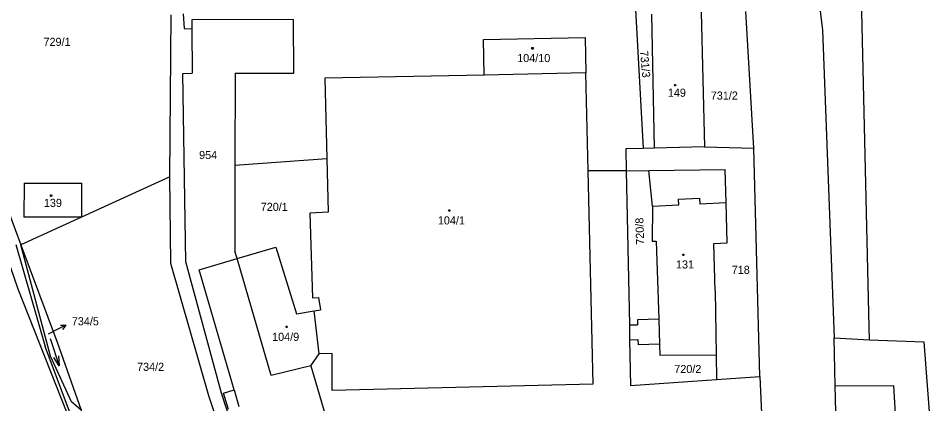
# Model space of a CAD drawing. Extents: x -580551 to -575069, y -1073031 to -1067931.
# Drawn here: x -578576.7 to -578385, y -1071122.8 to -1071041.9 of the extents above; entities that cross this region are included whole.
import ezdxf

# ---------------------------------------------------------------- set-up
doc = ezdxf.new("R2010")
doc.units = 0
for name, color, linetype in [('Druh pozemku', 7, 'Continuous'), ('Hranice z rastru', 7, 'Continuous'), ('Katastrální hranice', 7, 'Continuous'), ('Parcela', 7, 'Continuous'), ('Parcelní číslo', 7, 'Continuous'), ('Parcelní číslo_stavba', 7, 'Continuous'), ('Pomocná vrstva', 7, 'Continuous'), ('SR - hranice státu', 7, 'Continuous'), ('Vnitřní kresba', 7, 'Continuous')]:
    doc.layers.add(name, color=color, linetype=linetype)

msp = doc.modelspace()

# ---------------------------------------------------------------- linework, layer by layer
at = {"layer": 'Druh pozemku'}
msp.add_line((-578569.947, -1071109.134), (-578568.113, -1071114.846), dxfattribs=at)
for points in [[(-578468.59, -1071048.03), (-578468.5, -1071048.18), (-578468.59, -1071048.33), (-578468.77, -1071048.33), (-578468.86, -1071048.18), (-578468.77, -1071048.03)], [(-578438.64, -1071055.75), (-578438.55, -1071055.9), (-578438.64, -1071056.05), (-578438.82, -1071056.05), (-578438.91, -1071055.9), (-578438.82, -1071055.75)], [(-578569.69, -1071078.98), (-578569.6, -1071079.13), (-578569.69, -1071079.28), (-578569.87, -1071079.28), (-578569.96, -1071079.13), (-578569.87, -1071078.98)], [(-578486.06, -1071082.09), (-578485.97, -1071082.24), (-578486.06, -1071082.39), (-578486.24, -1071082.39), (-578486.33, -1071082.24), (-578486.24, -1071082.09)], [(-578436.92, -1071091.43), (-578436.83, -1071091.58), (-578436.92, -1071091.73), (-578437.1, -1071091.73), (-578437.19, -1071091.58), (-578437.1, -1071091.43)], [(-578520.25, -1071106.52), (-578520.16, -1071106.67), (-578520.25, -1071106.82), (-578520.43, -1071106.82), (-578520.52, -1071106.67), (-578520.43, -1071106.52)]]:
    msp.add_lwpolyline(points, close=True, dxfattribs=at)
msp.add_lwpolyline([(-578568.248, -1071112.789), (-578568.113, -1071114.846), (-578569.2, -1071113.095)], dxfattribs=at)
at = {"layer": 'Hranice z rastru'}
msp.add_lwpolyline([(-578566.72, -1070947.779), (-578583.48, -1070998.532), (-578590.876, -1071020.93), (-578592.521, -1071043.374), (-578590.032, -1071060.419), (-578576.797, -1071098.705), (-578560.811, -1071139.089), (-578544.825, -1071179.473), (-578532.639, -1071204.254), (-578528.184, -1071216.579), (-578534.736, -1071226.806), (-578537.749, -1071239.524), (-578532.246, -1071274.139), (-578521.632, -1071309.672), (-578516.391, -1071321.603), (-578520.977, -1071339.96), (-578529.232, -1071361.069)], dxfattribs=at)
at = {"layer": 'Katastrální hranice'}
for p in [(-578577.22, -1071089.4), (-578548.7, -1071170.29)]:
    msp.add_line(p, (-578571.03, -1071110.79), dxfattribs=at)
at = {"layer": 'Parcela'}
for p, q in [((-578397.99, -1071106.73), (-578400.72, -1070989.27)), ((-578412.58, -1071004.4), (-578407.76, -1071044.39)), ((-578447.49, -1071032.19), (-578445.44, -1071069.19)), ((-578433.24, -1071040.55), (-578432.57, -1071068.86)), ((-578422.17, -1071069.12), (-578423.85, -1071040.47)), ((-578544.84, -1071075.2), (-578544.59, -1071041.12)), ((-578542.03, -1071040.93), (-578541.87, -1071044.02)), ((-578518.86, -1071042.13), (-578540.23, -1071042.18)), ((-578540.23, -1071042.18), (-578540.22, -1071044.1)), ((-578518.81, -1071053.37), (-578518.86, -1071042.13)), ((-578443.08, -1071069.13), (-578443.65, -1071041)), ((-578541.87, -1071044.02), (-578540.22, -1071044.1)), ((-578540.22, -1071044.1), (-578540.18, -1071053.43)), ((-578407.76, -1071044.39), (-578405.35, -1071109.02)), ((-578478.99, -1071046.35), (-578457.64, -1071045.89)), ((-578478.81, -1071053.82), (-578478.99, -1071046.35)), ((-578457.64, -1071045.89), (-578457.47, -1071053.34)), ((-578542.14, -1071053.44), (-578540.18, -1071053.43)), ((-578541.52, -1071093.04), (-578542.14, -1071053.44)), ((-578531.15, -1071053.41), (-578531.17, -1071072.74)), ((-578531.15, -1071053.41), (-578518.81, -1071053.37)), ((-578478.81, -1071053.82), (-578512.32, -1071054.45)), ((-578457.47, -1071053.34), (-578478.81, -1071053.82)), ((-578456.99, -1071073.93), (-578457.47, -1071053.34)), ((-578512.32, -1071054.45), (-578511.88, -1071071.31)), ((-578445.44, -1071069.19), (-578449.1, -1071069.28)), ((-578449.1, -1071069.28), (-578449, -1071073.92)), ((-578443.08, -1071069.13), (-578445.44, -1071069.19)), ((-578432.57, -1071068.86), (-578443.08, -1071069.13)), ((-578432.57, -1071068.86), (-578422.17, -1071069.12)), ((-578420.92, -1071117.09), (-578422.17, -1071069.12)), ((-578531.17, -1071072.74), (-578511.88, -1071071.31)), ((-578511.88, -1071071.31), (-578511.58, -1071082.62)), ((-578531.17, -1071072.74), (-578531.18, -1071090.78)), ((-578449, -1071073.92), (-578456.99, -1071073.93)), ((-578455.93, -1071118.76), (-578456.99, -1071073.93)), ((-578449, -1071073.92), (-578444.22, -1071073.85)), ((-578449, -1071073.92), (-578448.34, -1071106.3)), ((-578444.22, -1071073.85), (-578428.22, -1071073.62)), ((-578443.49, -1071081.32), (-578444.22, -1071073.85)), ((-578428.01, -1071080.57), (-578428.22, -1071073.62)), ((-578580.97, -1071076.59), (-578576.15, -1071089.49)), ((-578575.45, -1071076.47), (-578575.48, -1071083.62)), ((-578575.45, -1071076.47), (-578563.39, -1071076.52)), ((-578544.84, -1071075.2), (-578563.43, -1071083.68)), ((-578563.39, -1071076.52), (-578563.43, -1071083.68)), ((-578544.61, -1071093.4), (-578544.84, -1071075.2)), ((-578427.78, -1071089.05), (-578428.01, -1071080.57)), ((-578511.58, -1071082.62), (-578515.44, -1071082.83)), ((-578443.49, -1071081.32), (-578443.56, -1071088.67)), ((-578563.43, -1071083.68), (-578576.15, -1071089.49)), ((-578563.43, -1071083.68), (-578575.48, -1071083.62)), ((-578515.44, -1071082.83), (-578514.89, -1071100.58)), ((-578576.15, -1071089.49), (-578568.52, -1071109.92)), ((-578569.88, -1071112.88), (-578576.15, -1071089.49)), ((-578530.74, -1071092.35), (-578522.6, -1071089.94)), ((-578522.6, -1071089.94), (-578518.22, -1071103.96)), ((-578443.56, -1071088.67), (-578442.68, -1071088.67)), ((-578442.68, -1071088.67), (-578442.15, -1071105.06)), ((-578430.61, -1071089.18), (-578427.78, -1071089.05)), ((-578430.32, -1071099.09), (-578430.61, -1071089.18)), ((-578538.67, -1071094.7), (-578530.74, -1071092.35)), ((-578530.74, -1071092.35), (-578531.18, -1071090.78)), ((-578523.58, -1071116.91), (-578530.74, -1071092.35)), ((-578536.67, -1071121.21), (-578544.61, -1071093.4)), ((-578534.03, -1071120.61), (-578541.52, -1071093.04)), ((-578531.32, -1071119.94), (-578538.67, -1071094.7)), ((-578430.32, -1071099.09), (-578430.1, -1071112.59)), ((-578514.89, -1071100.58), (-578513.63, -1071100.54)), ((-578513.63, -1071100.54), (-578513.21, -1071103.13)), ((-578518.22, -1071103.96), (-578514.56, -1071103.35)), ((-578514.56, -1071103.35), (-578513.21, -1071103.13)), ((-578513.5, -1071112.37), (-578514.56, -1071103.35)), ((-578442.15, -1071105.06), (-578446.64, -1071105.18)), ((-578446.64, -1071105.18), (-578446.61, -1071106.26)), ((-578448.34, -1071106.3), (-578446.61, -1071106.26)), ((-578448.34, -1071106.3), (-578448.28, -1071109.4)), ((-578397.93, -1071109.39), (-578397.99, -1071106.73)), ((-578448.28, -1071109.4), (-578446.54, -1071109.36)), ((-578448.28, -1071109.4), (-578448.08, -1071119.03)), ((-578446.54, -1071109.36), (-578446.51, -1071110.45)), ((-578405.35, -1071109.02), (-578397.93, -1071109.39)), ((-578405.11, -1071119.06), (-578405.35, -1071109.02)), ((-578397.93, -1071109.39), (-578386.49, -1071109.82)), ((-578568.52, -1071109.92), (-578563.47, -1071124.19)), ((-578441.98, -1071110.33), (-578446.51, -1071110.45)), ((-578441.98, -1071110.33), (-578441.91, -1071112.63)), ((-578386.49, -1071109.82), (-578385.04, -1071129.14)), ((-578565.51, -1071122.46), (-578569.88, -1071112.88)), ((-578515.21, -1071114.91), (-578513.5, -1071112.37)), ((-578510.79, -1071112.29), (-578513.5, -1071112.37)), ((-578510.75, -1071120.06), (-578510.79, -1071112.29)), ((-578441.91, -1071112.63), (-578430.1, -1071112.59)), ((-578430.1, -1071112.59), (-578430.02, -1071117.74)), ((-578515.21, -1071114.91), (-578523.58, -1071116.91)), ((-578515.21, -1071114.91), (-578506.34, -1071145.08)), ((-578430.02, -1071117.74), (-578420.92, -1071117.09)), ((-578420.92, -1071117.09), (-578420.49, -1071126.46)), ((-578455.93, -1071118.76), (-578510.75, -1071120.06)), ((-578448.08, -1071119.03), (-578430.02, -1071117.74)), ((-578404.66, -1071137.52), (-578405.11, -1071119.06)), ((-578512.07, -1071187.59), (-578534.03, -1071120.61)), ((-578533.56, -1071120.59), (-578531.32, -1071119.94)), ((-578532.55, -1071124.08), (-578533.56, -1071120.59)), ((-578563.47, -1071124.19), (-578565.51, -1071122.46)), ((-578532.82, -1071132.45), (-578536.67, -1071121.21))]:
    msp.add_line(p, q, dxfattribs=at)
at = {"layer": 'Pomocná vrstva'}
for p in [(-578570.36, -1071108.14), (-578566.677, -1071106.369)]:
    msp.add_line(p, (-578569.38, -1071107.67), dxfattribs=at)
msp.add_lwpolyline([(-578567.795, -1071106.352), (-578566.677, -1071106.369), (-578567.361, -1071107.253)], dxfattribs=at)
at = {"layer": 'SR - hranice státu'}
msp.add_lwpolyline([(-578586.18, -1071013.95), (-578588.3, -1071042.01), (-578586.77, -1071057.49), (-578582.9, -1071071.43), (-578580.97, -1071076.59), (-578576.15, -1071089.49), (-578568.52, -1071109.92), (-578563.47, -1071124.19), (-578556.68, -1071143.37)], dxfattribs=at)
at = {"layer": 'Vnitřní kresba'}
for p, q in [((-578437.99, -1071079.86), (-578433.62, -1071079.65)), ((-578437.93, -1071081.05), (-578437.99, -1071079.86)), ((-578433.62, -1071079.65), (-578433.57, -1071080.84)), ((-578433.57, -1071080.84), (-578428.01, -1071080.57)), ((-578443.49, -1071081.32), (-578437.93, -1071081.05)), ((-578442.15, -1071105.06), (-578441.98, -1071110.33)), ((-578405.11, -1071119.06), (-578392.88, -1071119.01)), ((-578392.88, -1071119.01), (-578391.78, -1071137.27)), ((-578531.32, -1071119.94), (-578530.33, -1071123.43))]:
    msp.add_line(p, q, dxfattribs=at)

# ---------------------------------------------------------------- texts
at = {"layer": 'Parcelní číslo'}
for s, height, p in [('729/1', 1.7, (-578571.382, -1071047.66)), ('731/2', 1.7, (-578431.239, -1071058.95)), ('954', 1.7, (-578538.706, -1071071.44)), ('720/1', 1.7, (-578525.765, -1071082.33)), ('718', 1.7, (-578426.839, -1071095.56)), ('734/5', 0.1, (-578570.567, -1071108.14)), ('734/2', 1.7, (-578551.736, -1071115.93)), ('720/2', 1.7, (-578438.907, -1071116.39))]:
    msp.add_text(s, height=height, dxfattribs=at).set_placement(p)
for s, rotation, p in [('731/3', 275.13433, (-578446.114, -1071048.731)), ('720/8', 91.84513, (-578445.22, -1071089.419))]:
    msp.add_text(s, height=1.7, rotation=rotation, dxfattribs=at).set_placement(p)
at = {"layer": 'Parcelní číslo_stavba'}
for s, p in [('104/10', (-578471.9, -1071051.07)), ('149', (-578440.247, -1071058.35)), ('139', (-578571.304, -1071081.5)), ('104/1', (-578488.559, -1071085.18)), ('131', (-578438.547, -1071094.43)), ('104/9', (-578523.376, -1071109.63))]:
    msp.add_text(s, height=1.7, dxfattribs=at).set_placement(p)
at = {"layer": 'Pomocná vrstva'}
msp.add_text('734/5', height=1.7, dxfattribs=at).set_placement((-578565.443, -1071106.37))

doc.saveas('drawing.dxf')
